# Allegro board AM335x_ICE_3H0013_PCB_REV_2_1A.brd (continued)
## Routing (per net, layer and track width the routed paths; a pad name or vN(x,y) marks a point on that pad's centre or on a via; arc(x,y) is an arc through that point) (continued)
GPMC_AD15: length 105.6
  TOP w0.121: U1.G6 v1(24.37,88.63) ; U14.U13 36.23,50.79 36.23,51.11 36.23,51.11 36.23,51.39 36.23,51.39 36.23,52.39 36.59,52.76 36.59,53.59 36.1,54.08 36.1,54.61 34.42,56.28 30.58,56.28 30.43,56.13 29.08,56.13 24.79,60.42 24.79,60.9 24.79,60.9 24.79,61.14 21.8,64.13 21.8,68.15 21.63,68.33 21.63,68.34 21.38,68.59 21.36,68.59 18.96,70.99 18.96,71.29 18.94,71.31 18.94,80.1 20.48,81.64 23.93,81.64 25,80.57 25.06,80.51 25.06,80.3 v1(25.22,80.14) 25.43,80.34 25.43,80.69 23.94,82.19 18.52,82.19 16.05,84.66 16.05,88.79 15.39,89.46 12.29,89.46 11.83,89.91 11.83,99.4 J4.29
  LYR4 w0.127: v1(25.22,80.14) 25.54,80.45 25.7,80.45 27.01,81.77 27.01,86.74 25.53,88.23 25.31,88.23 25.3,88.23 24.85,88.23 24.45,88.63 v1(24.37,88.63)
  BOTTOM w0.121: v1(25.22,80.14) 24.97,79.88 24.97,79.3 25.07,79.2 25.61,79.2 25.71,79.29 25.71,79.78 25.81,79.88 25.93,79.88 26.07,79.75 26.07,79.31 26.16,79.22 26.99,79.22 27.11,79.1 27.11,78.97 27,78.86 25.1,78.86 24.99,78.75 24.99,78.56 25.09,78.45 27.05,78.45 27.19,78.32 27.19,78.11 26.96,77.89 24.83,77.89 24.44,77.51 24.44,77.1 24.61,76.94 25.49,76.94 U26.26
GPMC_ADVN_ALE: length 76.6
  TOP w0.121: v1(41.77,49.25) U14.R7
  LYR3 w0.127: v1(41.77,49.25) 42.16,49.64 42.16,50.8 40.35,52.62 40.35,53.77 40.51,53.94 40.51,54.48 40.31,54.68 40.31,55.97 35.82,60.46 30.2,60.46 28.3,62.35 28.3,62.85 28.3,63.67 27.29,64.68 27.29,67.1 26.66,67.73 v1(26.64,67.73)
  LYR4 w0.127: J4.27 15.3,96.27 24.54,96.27 30.44,90.36 30.44,82.17 29.86,81.58 29.86,80.46 v1(26.77,77.37) 26.31,76.92 26.31,73.6 26.64,73.27 v1(26.64,67.73)
  BOTTOM w0.121: U26.25 v1(26.77,77.37) ; U26.48 26.2,68.17 v1(26.64,67.73)
GPMC_CSN0: length 49.5
  TOP w0.121: v1(28.64,82.18) 28.26,81.79 28.26,79.7 26.22,77.66 26.22,65.4 28.16,63.46 28.16,62.48 29.87,60.77 34.36,60.77 34.37,60.78 36,60.78 38.49,58.28 39.54,58.28 41.91,55.92 41.91,52.76 41.93,52.74 42.17,52.5 U14.V6 ; v1(23.57,83.83) U1.F1
  BOTTOM w0.121: v1(23.57,83.83) 24.21,83.19 28.31,83.19 R125.1 28.57,82.25 v1(28.64,82.18)
GPMC_CSN2: length 73.5
  TOP w0.121: U14.V9 40.01,51.49 40.01,53.49 39.72,53.77 39.72,54.43 39.74,54.45 39.74,55.28 38.56,56.46 37.53,56.46 35.6,58.38 29.45,58.38 26.25,61.58 26.25,62.27 v1(24.89,63.63)
  BOTTOM w0.121: J4.21 12.05,90.68 11.93,90.8 11.93,91.42 11.65,91.69 9.33,91.69 8.79,91.16 8.79,63.59 9.77,62.61 15.91,62.61 17.57,64.26 24.26,64.26 v1(24.89,63.63)
GPMC_NOR_A1: length 60.7
  TOP w0.121: v1(25.4,91.19) 30.06,86.53 30.06,81.92 29.7,81.55 29.61,81.55 29,80.94 29,71.01 27.57,69.58 27.57,65.41 29.07,63.91 29.07,62.75 30.3,61.51 33.87,61.51 33.88,61.51 36.61,61.51 39.11,59.02 39.94,59.02 40.16,58.8 40.95,58.8 43.08,56.67 43.08,54.12 43.43,53.77 v1(43.43,53.34) 43.43,53.21 43.37,53.15 43.37,50.85 U14.U5 ; U1.E6 v1(22.77,88.63)
  BOTTOM w0.121: v1(22.77,88.63) 22.77,89.32 24.77,91.32 25.26,91.32 v1(25.4,91.19) R102.2
GPMC_NOR_A2: length 57.4
  TOP w0.121: v1(19.57,84.63) U1.B2 ; v1(43.37,49.25) U14.R5
  LYR3 w0.127: v1(27.81,84.07) 29.12,82.77 29.12,71.2 28.56,70.64 28.56,66.37 27.87,65.69 27.87,65.27 28.56,64.58 28.56,62.53 30.2,60.88 36,60.88 40.82,56.07 40.82,53.92 40.58,53.68 40.58,53.02 42.98,50.62 42.98,49.64 v1(43.37,49.25)
  BOTTOM w0.121: R115.2 v1(27.81,84.07) 27.64,84.24 26.05,84.24 25.55,83.74 25.55,83.69 25.32,83.46 24.27,83.46 23.98,83.75 23.98,83.98 23.71,84.24 22.46,84.24 21.67,85.02 19.96,85.02 v1(19.57,84.63)
GPMC_OEN_REN: length 88.7
  TOP w0.121: v1(24.37,83.92) 24.29,83.92 U1.G1 ; v1(41.77,50.05) U14.T7
  LYR3 w0.127: v1(41.77,50.05) 41.77,50.58 39.89,52.46 39.89,53.45 39.73,53.62 39.73,53.93 39.72,53.93 39.72,54.26 39.9,54.44 39.9,55.84 35.66,60.08 30.04,60.08 26.86,63.26 26.86,66.92 26.22,67.56 26.22,68.35 26.97,69.1 26.97,72.16 27.91,73.11 27.91,78.74 28.32,79.15 28.32,81.69 28.13,81.88 28.13,81.89 27.92,82.11 27.92,83.31 27.23,84 27.23,87.58 25.04,89.76 22,89.76 ; v1(24.37,83.92) 24.45,83.92 24.78,84.24 24.78,85.58 23.98,86.38 23.98,88.97 23.54,89.41 22.35,89.41 22,89.76 ; 22,89.76 v1(21.92,89.76) 21.55,90.13 21.55,96.29 20.38,97.46 19.98,97.46 19.83,97.31 19.83,96.59 19.68,96.44 19.47,96.44 19.32,96.59 19.32,97.31 19.17,97.46 18.96,97.46 18.82,97.31 18.82,96.59 18.67,96.44 18.46,96.44 18.31,96.59 18.31,97.31 18.16,97.46 17.95,97.46 17.8,97.31 17.8,96.59 17.65,96.44 17.44,96.44 17.29,96.59 17.29,97.31 17.14,97.46 16.93,97.46 16.78,97.31 16.78,96.59 16.63,96.44 16.42,96.44 16.28,96.59 16.28,97.31 16.13,97.46 15.92,97.46 15.77,97.31 15.77,96.59 15.62,96.44 15.41,96.44 15.26,96.59 15.26,97.31 15.11,97.46 14.7,97.46 13.27,96.03 J4.25
GPMC_WEN: length 84.3
  TOP w0.121: U1.A4 v1(18.77,87.03) ; v1(19.38,90.73) 19.85,90.26 20.35,90.26 21.26,89.35 26.29,89.35 29.12,86.51 29.12,81.82 28.62,81.33 28.62,79.28 27.19,77.85 27.19,72.38 26.97,72.16 26.97,71.82 27.19,71.59 27.19,65.14 28.63,63.71 28.63,62.66 30.15,61.14 34.21,61.14 34.22,61.14 36.15,61.14 38.64,58.64 39.79,58.64 40,58.43 40.79,58.43 42.27,56.95 42.27,54.46 42.15,54.34 42.15,53.15 42.57,52.73 42.57,50.85 U14.U6
  LYR3 w0.127: J4.23 13.54,93.49 14.51,93.49 14.66,93.34 14.66,92.05 14.81,91.9 15.02,91.9 15.16,92.05 15.16,93.34 15.31,93.49 15.52,93.49 15.67,93.34 15.67,92.05 15.82,91.9 16.03,91.9 16.18,92.05 16.18,93.34 16.33,93.49 16.54,93.49 16.69,93.34 16.69,92.05 16.84,91.9 17.05,91.9 17.2,92.05 17.2,93.34 17.35,93.49 17.56,93.49 17.7,93.34 17.7,92.05 17.85,91.9 18.06,91.9 18.21,92.05 18.21,93.34 18.36,93.49 18.92,93.49 19.38,93.03 v1(19.38,90.73)
  BOTTOM w0.121: v1(19.38,90.73) 19.16,90.51 19.16,87.42 v1(18.77,87.03)
I2C0_SCL: length 250.6
  TOP w0.121: v1(3.08,61.68) 3.68,62.29 3.68,63.12 ; v1(33.77,38.85) U14.C16 ; R69.2 v1(11.43,21.34) ; U12.12 73.29,58.18 71.37,56.26 71.37,55.66 68.3,52.58 68.3,40.01 70.88,37.43 70.88,34.84 71.45,34.27 71.45,32.13 71.57,32.01 71.57,30.67 69.77,28.87 65.12,28.87 64.4,28.15 61.74,28.15 59.82,26.23 v1(59.82,25.78) 62.23,23.37 62.23,11.9 61.66,11.33 61.66,9.4 61.31,9.05 61.31,5.17 v1(58.8,2.67)
  LYR3 w0.127: v1(59.82,25.78) 59.4,26.2 50.04,26.2 48.65,24.81 43.97,24.81 42.57,26.21 37.8,26.21 37.31,26.69 36.91,26.69 36.66,26.45 36.66,26.28 v1(36.14,25.75) 36.14,25.77 35.71,26.19 31.24,26.19 30.65,26.79 28.96,26.79 27.07,24.9 22.44,24.9 21.2,23.66 17.92,23.66 16.88,22.62 12.71,22.62 v1(11.43,21.34)
  LYR4 w0.127: v1(36.14,25.75) 35.95,25.75 35.51,26.19 34.81,26.19 33.61,27.4 33.61,29.62 34.05,30.07 ; 34.05,30.07 v1(34.08,30.07) ; 34.05,30.07 34.05,30.52 33.75,30.82 33.75,32.26 34.21,32.71 34.21,36.71 33.77,37.15 v1(33.77,38.85) ; v1(11.43,21.34) 11.85,21.76 11.85,23.06 8.74,26.16 8.74,47.21 7.82,48.13 7.82,54.74 5.71,56.85 5.71,59.04 v1(3.08,61.68)
  BOTTOM w0.121: v1(3.08,61.68) 1.29,63.47 1.29,77.36 J3.6 3.71,79.78 3.71,93.97 8.63,98.9 8.63,100.65 10.08,102.1 17.84,102.1 21.08,98.86 v1(21.08,97.59) U25.6 ; v1(34.08,30.07) 34.04,30.02 34.04,29.72 R196.1 ; v1(59.82,25.78) U31.15 ; J17.5 59.06,2.93 v1(58.8,2.67)
I2C0_SDA: length 259.7
  TOP w0.121: v1(58.8,1.91) 58.38,2.32 58.38,3.52 59.9,5.04 59.9,8.8 60.62,9.51 60.62,11.34 61.09,11.81 61.09,22.48 v1(59.82,23.75) 59.18,24.38 59.18,26.29 62.14,29.25 63.55,29.25 63.7,29.1 63.73,29.1 63.75,29.09 64.27,29.09 64.28,29.1 64.84,29.1 65.55,29.81 68.37,29.81 71.21,32.65 71.21,34.08 70.63,34.65 70.63,36.98 67.88,39.73 67.88,52.58 71.01,55.71 71.01,56.63 73.21,58.83 U12.13 ; R72.2 14.99,21.08 14.99,21.95 v1(15.14,22.1) ; v1(30.18,26.14) 29.79,26.53 25.92,26.53 25.57,26.18 24.81,26.18 24.27,26.72 24.27,27.08 24.26,27.08 24.26,27.48 24.39,27.61 24.39,29.79 23.89,30.29 23.89,32.46 24.44,33 27.26,33 27.37,32.9 28.12,32.9 R61.1 28.98,33.76 29.7,33.76 30.43,34.49 30.43,35.37 31.79,36.73 31.79,37.35 32.43,37.99 32.59,37.99 32.97,38.37 32.97,38.85 U14.C17 ; U6.5 v1(2.41,65.51)
  LYR3 w0.127: v1(59.82,23.75) 58.71,22.64 45.77,22.64 43,25.41 41.94,25.41 41.52,24.99 31.69,24.99 30.54,26.14 v1(30.18,26.14) 29.79,26.54 29.17,26.54 27.29,24.65 22.69,24.65 21.41,23.37 18.59,23.37 17.59,22.36 15.91,22.36 15.64,22.1 v1(15.14,22.1)
  LYR4 w0.127: v1(2.41,65.51) 4.06,63.86 4.06,62.97 6.01,61.02 6.01,56.92 8.22,54.71 8.22,48.37 9,47.59 9,26.27 11.54,23.73 13.86,23.73 15.14,22.45 v1(15.14,22.1)
  BOTTOM w0.121: U25.7 v1(20.52,98.24) 20.52,99.06 17.73,101.85 10.18,101.85 8.95,100.62 8.95,98.56 6.81,96.42 6.81,93.02 5.98,92.2 4.28,92.2 3.95,91.87 3.95,77.49 J3.4 3.43,75.06 3.43,70.33 3.27,70.17 3.27,68.94 2.41,68.09 v1(2.41,65.51) ; U31.2 v1(59.82,23.75) ; 59.56,3.66 59.56,2.67 v1(58.8,1.91)
INDUS_INPUT0: length 8.8
  BOTTOM w0.121: J14.1 74.42,4.32 72.77,4.32 70.34,6.75 R226.1
INDUS_INPUT1: length 9.8
  TOP w0.121: R84.1 70.2,9.39 70.2,6.37 70.57,6 71.95,6 72.67,6.73 74.55,6.73 J14.3
INDUS_INPUT2: length 6.8
  TOP w0.121: R83.1 71.17,11.3 73.27,9.21 74.02,9.21 75.23,8 J14.5
INDUS_INPUT3: length 6.5
  TOP w0.121: J14.7 74.55,11.81 72.77,11.81 71.5,13.08 R81.1
INDUS_INPUT4: length 6.2
  TOP w0.121: J14.9 74.23,14.67 70.53,14.67 R80.1
INDUS_INPUT5: length 5.9
  TOP w0.121: R79.1 74.8,16.64 J14.11
INDUS_INPUT6: length 6.2
  TOP w0.121: J14.13 74.87,19.11 72.26,19.11 71.57,18.41 R74.1
INDUS_INPUT7: length 8.5
  TOP w0.121: R243.2 69.85,20.95 69.85,20.81 R68.1 71.38,20.31 72.14,19.56 74.68,19.56 J14.15
INDUS_INPUTSO: length 9.4
  TOP w0.121: U20.2 51.31,21.84 51.69,21.46 52.2,21.46 v1(53.85,19.81)
  BOTTOM w0.121: U35.23 57.24,17.79 57.02,18 57.02,18.88 56.09,19.81 v1(53.85,19.81)
IREF: length 3.1
  BOTTOM w0.121: J17.3 60.06,4.18 60.39,4.51 61.91,4.51 R232.1
JTAG_EMU0: length 109.9
  TOP w0.121: R25.1 75.43,67.01 74.8,67.64 72.21,67.64 72.02,67.45 72.02,67.24 v1(71.97,67.18) ; v1(35.37,38.85) U14.C14
  LYR3 w0.127: v1(20.83,28.45) 20.83,27.69 20.62,27.48 20.62,27.09 20.9,26.8 23.41,26.8 24.1,26.11 27.06,26.11 28.5,27.55 33.43,27.55 33.55,27.43 v1(34.16,27.43)
  LYR4 w0.127: v1(34.16,27.43) 34.16,27.71 33.86,28.01 33.86,29.25 34.69,30.08 34.69,32.83 35.47,33.61 35.47,33.96 34.98,34.45 34.98,38.46 v1(35.37,38.85) 35.6,38.85 36,38.45 36.33,38.45 36.57,38.21 36.57,37.09 42.67,30.99 48.97,30.99 49.57,30.39 52.84,30.39 53.18,30.05 59.31,30.05 59.65,30.39 60.27,30.39 61.71,31.84 64.55,31.84 66.34,33.63 66.34,34.62 68.13,36.41 68.35,36.41 69.15,37.21 69.15,57 69.4,57.26 69.4,64.62 v1(71.97,67.18)
  BOTTOM w0.121: J15.13 73.39,67.01 72.98,67.43 72.26,67.43 72.02,67.18 v1(71.97,67.18) ; R202.1 v1(20.83,28.45)
JTAG_EMU1: length 106.4
  TOP w0.121: v1(35.37,38.05) U14.B14 ; v1(72.26,65.49) 71.53,65.49 70.01,67.01 R24.1
  LYR3 w0.127: v1(21.13,25.53) 26.98,25.53 28.75,27.3 33.05,27.3 33.34,27.01 34.47,27.01 v1(34.82,27.36)
  LYR4 w0.127: v1(34.82,27.36) 34.82,27.41 34.11,28.12 34.11,29.04 35.01,29.94 35.01,32.2 35.01,32.21 35.01,32.55 35.01,32.56 35.01,32.79 35.72,33.5 35.72,35.52 35.37,35.88 v1(35.37,38.05) 35.69,37.73 35.69,37.62 42.57,30.73 48.74,30.73 49.33,30.14 52.74,30.14 53.08,29.8 59.42,29.8 59.76,30.14 60.37,30.14 61.82,31.58 65.01,31.58 66.85,33.43 66.85,34.12 67.3,34.57 67.62,34.57 67.91,34.86 67.91,35.6 69.4,37.1 69.4,56.9 69.66,57.15 69.66,63.82 71.32,65.49 v1(72.26,65.49)
  BOTTOM w0.121: J15.14 71.17,67.01 71.5,66.67 71.5,66.25 v1(72.26,65.49) ; R204.1 20.45,25.78 20.88,25.78 v1(21.13,25.53)
JTAG_TCK: length 113.2
  TOP w0.121: U14.A12 v1(36.97,37.25) ; v1(71.63,69.22) 71.75,69.22 72.77,70.23 75.18,70.23 75.47,69.94 R22.2 R23.2
  LYR3 w0.127: v1(17.72,33.25) 18.11,32.85 19,32.85 20.62,31.23 31.64,31.23 33.77,33.36 35.23,33.36 36.97,35.11 v1(36.97,37.25)
  LYR4 w0.127: v1(71.63,69.22) 69.15,66.73 69.15,57.4 68.89,57.15 68.89,37.31 68.25,36.66 68.03,36.66 65.84,34.48 65.84,33.76 64.33,32.25 60.79,32.25 59.86,31.31 59.86,31.25 58.91,30.3 53.29,30.3 52.95,30.65 49.9,30.65 49.3,31.24 42.98,31.24 v1(36.97,37.25)
  BOTTOM w0.121: v1(17.72,33.25) 17.66,33.19 17.66,27.76 15.36,25.46 14.59,25.46 13.46,24.34 R209.1
JTAG_TDI: length 99.9
  TOP w0.121: U14.B11 v1(37.77,38.05)
  LYR3 w0.127: v1(37.77,38.05) 38.16,37.66 38.16,33.85 36.03,31.71 v1(36.03,31.57)
  LYR4 w0.127: v1(37.77,38.05) 38.61,37.21 38.61,36.63 41.87,33.37 44.02,33.37 44.87,32.51 45.72,32.51 46.32,31.92 49.73,31.92 49.91,31.74 58.13,31.74 58.31,31.92 59.73,31.92 60.6,32.79 62.61,32.79 68.39,38.57 68.39,57.53 68.64,57.78 68.64,69.42 71.37,72.15 72.15,72.15 v1(72.9,72.9)
  BOTTOM w0.121: J15.3 73.36,73.36 v1(72.9,72.9) ; R192.1 20.5,30.81 29.08,30.81 29.15,30.88 29.17,30.88 29.19,30.89 29.19,30.89 29.97,30.89 30.35,31.27 32.57,31.27 33.19,31.9 34.59,31.9 35.21,31.27 35.73,31.27 v1(36.03,31.57)
JTAG_TDO: length 98
  TOP w0.121: U14.A11 v1(37.77,37.25)
  LYR3 w0.127: v1(36.02,32.41) 36.36,32.75 36.6,32.75 37.77,33.92 v1(37.77,37.25)
  LYR4 w0.127: v1(37.77,37.25) 38.35,36.66 38.35,36.53 42.69,32.19 45.15,32.19 45.69,31.66 49.48,31.66 50.15,30.99 53.32,30.99 53.66,30.65 56.99,30.65 57.59,31.24 58.52,31.24 58.86,31.58 59.76,31.58 60.7,32.53 62.71,32.53 68.64,38.46 68.64,57.4 68.89,57.66 68.89,68.97 71.25,71.33 72.73,71.33 v1(72.77,71.37)
  BOTTOM w0.121: R190.1 20.4,32 20.55,31.85 20.55,31.69 20.97,31.27 21.13,31.27 21.35,31.05 28.97,31.05 29.06,31.14 29.47,31.14 30.1,31.77 32.71,31.77 33.09,32.14 34.46,32.14 35.11,32.8 35.6,32.8 35.99,32.41 v1(36.02,32.41) ; v1(72.77,71.37) 73.32,70.82 J15.7
JTAG_TMS: length 102.3
  TOP w0.121: v1(37.77,38.85) U14.C11
  LYR3 w0.127: v1(37.77,38.85) 37.58,38.85 37.18,38.45 36.81,38.45 36.58,38.21 36.58,37.89 36.82,37.64 37.13,37.64 37.36,37.41 37.36,34.77 35.65,33.06 34.17,33.06 32,30.9 21.93,30.9 21.18,30.15 v1(21.1,30.15)
  LYR4 w0.127: v1(72.8,74.76) 70.65,74.76 66.63,70.74 66.63,64.14 67.91,62.86 67.91,57.81 67.88,57.78 67.88,38.92 62.76,33.81 60.47,33.81 60.12,33.45 57.95,33.45 57.93,33.44 55.28,33.44 54.79,32.95 54.3,32.95 54.16,33.08 52.51,33.08 51.98,33.62 44.93,33.62 44.12,34.42 42.31,34.42 37.89,38.85 v1(37.77,38.85)
  BOTTOM w0.121: v1(72.8,74.76) 74.68,74.76 J15.1 ; R194.1 20.93,29.97 v1(21.1,30.15)
JTAG_TRSTN: length 113.9
  TOP w0.121: R14.2 73.31,74.5 v1(72.8,74) ; v1(35.73,30.16) 35.73,30.27 36.44,30.98 36.44,32.84 36.07,33.21 36.07,34.84 38.57,37.34 38.57,38.05 U14.B10
  LYR4 w0.127: v1(72.28,62.14) 71.84,61.7 71.84,55.33 71.88,55.29 71.88,48.43 71.01,47.56 71.01,38.77 70.62,38.38 70.62,34.36 69.43,33.16 69.43,31.39 67.85,29.81 67.62,29.81 67.06,29.25 61.13,29.25 60.47,28.59 58.57,28.59 58.21,28.23 53.5,28.23 52.48,29.25 45.91,29.25 45.79,29.37 45.39,29.76 36.13,29.76 v1(35.73,30.16)
  BOTTOM w0.121: v1(72.28,62.14) 72.68,62.54 72.68,65.79 71.75,66.72 71.75,66.78 71.43,67.1 71.43,67.45 71.63,67.65 71.73,67.65 72.26,68.18 72.26,68.2 72.27,68.2 72.27,68.7 72.26,68.71 72.26,73.19 72.26,73.46 v1(72.8,74) 72.17,74.63 J15.2 ; R201.1 21.08,28.96 22.61,30.48 29.1,30.48 29.25,30.63 29.27,30.64 29.29,30.64 29.29,30.64 29.64,30.64 29.65,30.63 30.61,30.63 30.85,30.87 32.52,30.87 33.3,31.65 34.49,31.65 35.05,31.09 35.05,30.47 35.36,30.16 v1(35.73,30.16)
LATCH0_IN: length 59.4
  TOP w0.121: U14.D18 30.9,38.38 30.9,37.77 30.16,37.03 30.16,36.86 29.8,36.5 25.37,36.5 v1(24.52,37.35)
  LYR3 w0.127: v1(24.52,37.35) 22.12,39.75 18.67,39.75 15.79,42.63 15.79,54.05 11.43,58.41 11.43,63.01 7.24,67.2 7.24,74.3 5.52,76.01 J3.3
LATCH1_IN: length 64.5
  TOP w0.121: U14.D17 32.97,39.65 32.97,39.17 32.71,38.91 32.55,38.91 31.56,37.92 31.56,37.01 30.56,36.01 24.68,36.01 v1(23.62,37.07)
  LYR3 w0.127: v1(23.62,37.07) 21.92,38.77 19.01,38.77 15.44,42.35 15.44,53.44 10.38,58.5 10.38,61.53 5.46,66.45 5.46,70.95 3.93,72.49 3.93,77.46 J3.5
LCD_BST_CONV_CTL: length 65.7
  TOP w0.121: v1(34.57,41.25) U14.F15
  LYR3 w0.127: v1(34.57,41.25) 34.33,41.25 33.93,40.86 33.62,40.86 33.25,40.49 33.25,40.38 32.24,39.37 30.48,39.37 v1(30.35,39.24)
  LYR4 w0.127: v1(52.45,9.4) 49.95,11.9 31.07,11.9 30.82,12.15 30.82,14.72 33.87,17.77 35.39,17.77 35.88,18.25 35.88,19.95 35.39,20.43 35.15,20.68 31.02,20.68 29.56,22.13 29.56,24.26 29.8,24.5 29.8,25.93 29.76,25.96 29.76,29.28 29.59,29.46 29.59,29.83 29.37,30.04 29.37,31.44 28.79,32.02 28.79,32.41 29.27,32.9 29.27,36.23 30.64,37.59 30.64,38.96 v1(30.35,39.24)
  BOTTOM w0.121: R225.2 v1(52.45,9.4)
LED_1: length 111
  TOP w0.121: v1(34.57,45.25) U14.K15
  LYR3 w0.127: v1(26.37,42.69) 26.37,42.84 27.22,43.69 29.87,43.69 30.12,43.43 33.02,43.43 33.2,43.26 34.73,43.26 34.96,43.49 34.96,44.86 v1(34.57,45.25)
  BOTTOM w0.121: Q2.5 75.34,92.72 75.6,92.47 R107.2 77.12,91.84 77.12,89.21 75.72,87.81 72.52,87.81 71.68,88.65 69.69,88.65 67.76,90.57 65.39,90.57 64.98,90.16 64.98,89.43 62.62,87.07 58.54,87.07 58.38,87.23 57.45,87.23 57.28,87.07 53.36,87.07 52.06,88.38 47.67,88.38 45.21,85.92 45.21,82.55 43.55,80.89 43.55,78.2 40.37,75.02 36.81,75.02 36.81,75.02 33.77,75.02 32.28,73.53 32.28,71.6 32.54,71.33 32.54,68.57 32.14,68.16 32.14,64.36 32.08,64.29 32.08,62.16 28.71,58.79 28.71,55.81 26.4,53.5 26.4,46.99 25.59,46.18 25.59,43.58 25.4,43.4 25.4,42.67 25.65,42.42 26.1,42.42 v1(26.37,42.69)
LED_2: length 105.1
  TOP w0.121: v1(26.12,45.71) 27.62,44.21 29.86,44.21 30.22,43.86 31.67,43.86 31.86,44.05 U14.J18
  LYR4 w0.127: v1(70.4,86.87) 70.03,87.24 70.03,87.79 72.64,90.41 72.64,94.24 71.74,95.14 v1(71.41,95.14)
  BOTTOM w0.121: Q1.2 v1(71.41,95.14) R104.2 ; v1(26.12,45.71) 26.12,45.75 26.85,46.48 26.85,52.01 28.69,53.85 28.69,55.38 29.03,55.71 29.03,58.64 32.32,61.94 32.32,64.19 32.39,64.26 32.39,68.06 32.79,68.46 32.79,71.44 32.64,71.59 32.64,73.53 33.15,74.04 33.66,74.04 34.67,73.03 36.45,73.03 36.83,73.41 40.29,73.41 44.98,78.1 44.98,80.67 47.43,83.12 47.43,84.84 47.25,85.01 47.25,87.61 47.77,88.13 51.95,88.13 53.26,86.82 53.59,86.82 53.59,86.82 57.38,86.82 57.55,86.99 58.28,86.99 58.44,86.82 62.72,86.82 65.23,89.33 65.23,90.06 65.44,90.27 67.71,90.27 69.16,88.82 69.16,88.11 v1(70.4,86.87) R126.2
LED_3: length 102.9
  TOP w0.121: U14.K18 32.48,44.94 28.62,44.94 27.69,45.87 27.69,50.2 27.48,50.4 27.48,53.01 27.91,53.44 27.91,55.6 v1(28.19,55.88)
  BOTTOM w0.121: v1(28.19,55.88) 27.78,56.3 27.78,58.48 30.4,61.1 30.4,65.46 30.27,65.59 30.27,66.18 30.73,66.64 30.73,67.1 32.3,68.67 32.3,70.95 32.03,71.21 32.03,73.02 31.92,73.12 31.92,74.77 32.42,75.26 36.07,75.26 36.9,76.09 40.43,76.09 42.73,78.39 42.73,80.45 44.96,82.68 44.96,86.02 47.56,88.62 52.16,88.62 53.47,87.32 57.18,87.32 57.34,87.48 58.48,87.48 58.65,87.32 62.52,87.32 64.71,89.51 64.71,90.9 66.39,92.59 67.35,92.59 67.97,93.21 67.97,94.66 67.86,94.77 67.86,96.11 68.83,97.09 75.5,97.09 75.96,97.55 76.75,97.55 77.47,96.82 77.47,96.12 R103.2 Q1.5
LED_4: length 78.2
  TOP w0.121: v1(40.11,54.1) 40.26,53.95 40.26,51.42 40.23,51.39 40.23,50.91 U14.U9 ; v1(47.24,64.26) 46.86,63.88 TP37.1
  LYR4 w0.127: v1(50.42,71.88) 50.42,69.26 48.73,67.57 48.73,65.75 v1(47.24,64.26) 46.88,63.9 46.88,61.33 46.17,60.62 45.76,60.62 43.34,58.2 43.34,57.95 40.11,54.72 v1(40.11,54.1) ; v1(75.72,88.4) 73.77,86.45 70.23,86.45 70.19,86.49 v1(67.44,86.49)
  BOTTOM w0.121: v1(75.72,88.4) 76.49,89.17 R109.2 76.36,90.31 Q3.2 ; v1(67.44,86.49) 67.31,86.61 64.38,86.61 64.34,86.57 58.34,86.57 58.17,86.74 57.65,86.74 57.48,86.57 53.13,86.57 51.82,87.88 47.87,87.88 47.5,87.51 47.5,86.99 47.68,86.81 47.68,82.42 47.54,82.28 47.54,76.77 49.37,74.94 49.37,72.93 49.83,72.48 49.83,72.45 50.1,72.18 50.12,72.18 v1(50.42,71.88)
MDIO_CLK: length 17.1
  TOP w0.121: U14.M18 31.43,47.59 31.43,47.8 28.84,50.4 28.84,52.29 v1(29.25,52.7)
  BOTTOM w0.121: R149.2 29.53,55.56 29.53,55.03 29.25,54.75 v1(29.25,52.7)
MDIO_DATA: length 19.5
  TOP w0.121: U14.M17 32.97,46.85 32.49,46.85 31.88,47.46 31.88,48.61 30.44,50.04 30.35,50.04 29.42,50.97 v1(29.36,50.97)
  BOTTOM w0.121: R147.2 36.07,59.44 35.71,59.08 35.71,58.94 35.3,58.53 34.73,58.53 34.72,58.54 33.26,58.54 30.03,55.31 30.03,54.83 29.84,54.63 29.84,51.56 29.36,51.08 v1(29.36,50.97)
MMC0_CLK: length 57.8
  TOP w0.121: U24.6 17.18,3.46 v1(17.18,4.06) ; R58.1 26.29,40.13 v1(25.91,40.51)
  LYR4 w0.127: v1(25.91,40.51) 25.4,40.01 25.4,37.78 25.74,37.44 25.74,34.42 25.57,34.24 25.57,31.47 26.23,30.81 26.23,27.45 26.45,27.22 26.45,26.01 26,25.56 26,24.74 25.17,23.91 25.17,19.81 26.5,18.48 26.5,8.88 22.52,4.89 19.83,4.89 19.47,4.53 18.97,4.53 18.83,4.39 18.83,2.93 18.61,2.71 18.36,2.71 18.25,2.82 18.25,3.86 18.13,3.97 17.81,3.97 17.7,3.86 17.7,2.82 17.59,2.71 17.31,2.71 17.18,2.84 v1(17.18,4.06)
  BOTTOM w0.121: v1(17.18,4.06) 17.18,3.91 17.38,3.71 17.38,2.95 16.66,2.22 16.2,2.22 15.87,2.54 15.19,2.54 15.07,2.66 J16.5 13.97,2.66 13.08,1.78 R237.1
MMC0_CMD: length 65.8
  TOP w0.121: U24.3 18.76,2.95 19.21,3.4 19.59,3.4 19.81,3.18 19.85,3.18 v1(19.86,3.19) ; U14.G18 31.29,42.45 30.75,41.91 28.96,41.91 27.97,40.92 v1(27.97,40.47)
  LYR4 w0.127: v1(19.86,3.19) 19.86,2.88 20.27,2.47 20.62,2.47 21.66,3.51 26.88,3.51 29.43,6.06 29.43,16.47 28.34,17.56 28.34,18.88 27.79,19.43 27.79,21.94 27.24,22.49 27.24,25.36 27.47,25.59 27.47,27.65 27.24,27.87 27.24,31.23 27.14,31.34 27.14,33.1 27.35,33.31 27.35,39.85 v1(27.97,40.47)
  BOTTOM w0.121: v1(19.86,3.19) 19.84,3.19 20.04,3.39 29.07,3.39 J16.3 30.16,3.36 30.23,3.3 R235.1
MMC0_DAT0: length 65.4
  TOP w0.121: U24.7 16.84,2.95 v1(16.46,3.33) ; U14.G16 33.76,42.04 33.28,42.04 32.91,41.67 32.91,41.51 32.71,41.31 32.29,41.31 30.62,39.63 29.94,39.63 29,38.69 25.29,38.69 v1(24.83,38.23)
  LYR4 w0.127: v1(16.46,3.33) 16.65,3.51 16.65,4.25 17.46,5.06 19.07,5.06 19.57,5.55 19.57,6.45 19.71,6.6 20.25,6.6 20.36,6.49 20.36,5.74 20.47,5.63 20.63,5.63 20.74,5.74 20.74,6.49 20.85,6.6 21.01,6.6 21.12,6.49 21.12,5.74 21.23,5.63 21.39,5.63 21.5,5.74 21.5,6.49 21.62,6.6 21.77,6.6 21.88,6.49 21.88,5.74 22,5.63 22.15,5.63 22.27,5.74 22.27,6.49 22.38,6.6 23.43,6.6 26,9.17 26,18.27 24.17,20.1 24.17,23.86 25.49,25.18 25.49,25.77 25.95,26.22 25.95,27.01 25.72,27.24 25.72,30.6 25.06,31.26 25.06,34.46 25.23,34.63 25.23,37.23 24.83,37.64 v1(24.83,38.23)
  BOTTOM w0.121: v1(16.46,3.33) 15.73,4.06 J16.7 13.97,4.06 R236.1
MMC0_DAT1: length 64.9
  TOP w0.121: v1(16.4,2.72) 16.68,2.45 U24.8 ; v1(34.57,42.05) U14.G15
  LYR4 w0.127: v1(26.42,41.29) 25.96,41.29 24.1,39.43 24.1,37.11 24.98,36.23 24.98,34.79 24.8,34.61 24.8,30.44 25.46,29.78 25.46,27.14 25.69,26.91 25.69,26.33 25.28,25.92 24.9,25.92 23.36,24.38 23.36,24.38 23.36,22.49 23.2,22.34 23.2,20.37 25.34,18.24 25.34,10 22.41,7.07 19.05,7.07 15.9,3.93 15.9,3.51 15.92,3.5 15.92,3.21 v1(16.4,2.72)
  BOTTOM w0.121: v1(26.42,41.29) 26.91,41.79 28.92,41.79 29.4,41.3 30.04,41.3 30.4,41.66 32.64,41.66 33.03,42.05 v1(34.57,42.05) ; v1(16.4,2.72) 16.59,2.91 16.64,2.91 16.88,3.15 16.88,3.5 15.61,4.76 J16.8 14.16,4.76 13.72,4.32 13.08,4.32 R234.1
MMC0_DAT2: length 66.9
  TOP w0.121: U24.1 19.4,1.95 20.34,2.89 v1(20.45,2.89) ; v1(25.91,39.11) 28.82,39.11 30.29,40.58 30.73,40.58 31.81,41.65 U14.F18
  LYR4 w0.127: v1(25.91,39.11) 27.09,37.93 27.09,33.41 26.88,33.2 26.88,31.23 26.99,31.13 26.99,27.77 27.22,27.54 27.22,25.7 26.84,25.32 26.84,19.87 27.61,19.09 27.61,8.16 23.43,3.98 21.53,3.98 v1(20.45,2.89)
  BOTTOM w0.121: R231.1 30.23,5.33 29.66,4.76 J16.1 19.75,4.76 18.92,3.93 18.92,2.77 19.17,2.53 20.05,2.53 20.42,2.89 v1(20.45,2.89)
MMC0_DAT3: length 65.5
  TOP w0.121: v1(19.34,2.94) 18.84,2.45 U24.2 ; U14.F17 32.97,41.25 32.97,40.77 32.71,40.51 32.55,40.51 30.63,38.59 30.63,37.93 29.94,37.23 29.94,36.96 29.71,36.73 29.34,36.73 27.84,38.22 v1(26.07,38.22)
  LYR4 w0.127: v1(19.34,2.94) 19.4,3.01 19.4,3.73 20.06,4.39 22.79,4.39 27.11,8.71 27.11,18.88 26.58,19.41 26.58,25.42 26.96,25.8 26.96,27.44 26.73,27.66 26.73,31.02 26.63,31.13 26.63,36.79 26.25,37.16 26.25,37.65 26.07,37.83 v1(26.07,38.22)
  BOTTOM w0.121: v1(19.34,2.94) 19.34,3.88 19.84,4.38 20.19,4.38 20.5,4.06 J16.2 29.97,4.06 30.23,4.32 R233.1
MUX_MII_CTL1: length 47.5
  TOP w0.121: U9.1 33.26,66.54 33.53,66.8 33.53,67.81 v1(33.74,68.03) ; v1(31.15,55.7) 29.02,55.7 28.57,55.25 28.57,53.46 27.73,52.62 27.73,50.5 28.16,50.07 28.16,46.56 28.66,46.06 29.88,46.06 30.28,45.65 U14.L18 ; v1(43.98,64.12) 43.98,63.68 U11.1
  LYR4 w0.127: v1(31.15,55.7) 31.15,55.85 31.19,55.88 31.19,60.3 32.33,61.43 32.33,64.35 33.57,65.59 33.57,67.5 33.7,67.64 33.7,67.99 v1(33.74,68.03)
  BOTTOM w0.121: v1(33.74,68.03) 34.21,68.03 34.67,67.57 34.67,67.36 35.54,66.49 35.54,64.07 36.62,62.99 39.85,62.99 41.25,64.39 42.94,64.39 42.95,64.39 43.7,64.39 v1(43.98,64.12)
Net_52: length 0.6
  TOP w0.121: v1(19.57,85.43) 19.97,85.83
Net_53: length 0.6
  TOP w0.121: 20.77,86.63 v1(20.37,87.03)
Net_54: length 0.6
  TOP w0.121: v1(21.17,85.43) 21.57,85.83
NOR_READY: length 1.8
  TOP w0.121: v1(18.77,85.43) U1.A3
  BOTTOM w0.121: v1(18.77,85.43) 18.1,86.11 R111.1
NOR_RP: length 4.1
  TOP w0.121: U1.B4 v1(19.57,87.03)
  BOTTOM w0.121: R105.2 19.96,89.94 19.96,87.42 v1(19.57,87.03)
OSC0_OUT: length 8.2
  TOP w0.121: v1(37.85,55.11) 37.86,55.11 38.23,54.74 38.23,54.4 38.35,54.28 38.35,51.82 38.53,51.64 38.53,50.81 U14.U11
  BOTTOM w0.121: R156.1 35.56,56.2 36.09,55.67 36.09,55.24 36.23,55.11 v1(37.85,55.11)
OSC0_OUT1: length 9.2
  BOTTOM w0.121: C99.1 R156.2 36.13,57.28 36.14,57.29 36.79,57.29 Y3.1 37.13,57.93 37.87,58.67 40.9,58.67 41.91,57.67 R172.1
OSC1_IN: length 13.6
  TOP w0.121: U14.A6 42.49,37.33 42.49,35.05 42.75,34.79 42.76,34.79 43.06,34.5 43.06,32.81 43.26,32.61 43.26,29.1 42.67,28.51 42.67,27.99 v1(42.69,27.96) 42.95,27.96 43.05,28.07 C42.2
  BOTTOM w0.121: v1(42.69,27.96) 42.69,27.93 42.94,27.69 43.4,27.69 Y4.4
OSC1_OUT: length 4.7
  TOP w0.121: R64.1 44.83,33.4 44.83,33.41 44.7,33.53 44.7,33.54 44.41,33.83 44.41,34.59 43.77,35.22 U14.A4
OSC1_OUT1: length 3.9
  TOP w0.121: R64.2 v1(44.83,31.71) 44.58,31.46 C40.2
  BOTTOM w0.121: v1(44.83,31.71) 44.77,31.71 43.81,30.76 43.81,30.64 Y4.1
PGOOD_VTT: length 9.3
  TOP w0.121: TP22.1 69.89,43.86 v2(69.89,43.35)
  BOTTOM w0.121: U29.9 68.83,37.41 69.15,37.74 69.15,38.04 69.2,38.1 69.2,40.6 69.6,40.99 R184.1 69.6,43.05 v2(69.89,43.35)
PH: length 1.4
  TOP w0.635: C56.2 43.81,16.51
PMIC_I2C_SCL: length 10.1
  TOP w0.121: R69.1 R70.1 13.08,18.92 13.84,18.92 15.88,16.88 15.88,16.81 16.13,16.56 16.13,13.72 16.65,13.19 U22.9
PMIC_I2C_SDA: length 9
  TOP w0.121: R71.1 R72.1 14.48,18.8 16.13,17.14 16.13,16.91 16.38,16.66 16.38,13.84 17.05,13.17 U22.8
PMIC_INTN: length 8.6
  TOP w0.121: U22.45 21.45,10.65 22.35,11.56 22.35,16.26 TP27.1
PMIC_PWR_EN: length 48.6
  TOP w0.121: v1(20.7,13.21) 20.12,12.63 U22.1 ; v1(42.57,38.85) U14.C6
  LYR3 w0.127: v1(20.7,13.21) 30.3,13.21 31.19,12.32 v1(31.24,12.32)
  LYR4 w0.127: v1(42.21,24.97) 39.5,22.26 39.5,16.86 34.95,12.32 v1(31.24,12.32)
  BOTTOM w0.121: v1(42.21,24.97) 41.87,25.32 41.87,27.46 41.98,27.58 41.98,27.76 41.98,27.81 42.17,28 42.17,28.02 42.19,28.04 42.19,28.17 42.31,28.29 42.31,28.4 42.37,28.45 42.37,29 42.27,29.1 42.27,29.18 42.22,29.23 42.22,32.15 42.52,32.45 44.01,32.45 44.19,32.63 44.19,33.15 43.94,33.41 43.94,35.94 42.97,36.92 42.97,38.45 v1(42.57,38.85)
PMIC_RESETOUTN: length 49.2
  TOP w0.121: U14.B15 v1(34.57,38.05) ; v1(21.84,8.38) 21.57,8.65 U22.40
  LYR3 w0.127: v1(22.86,34.67) 28.27,34.67 29.54,35.95 33.64,35.95 34.57,36.87 v1(34.57,38.05)
  LYR4 w0.127: v1(22.86,34.67) 22.44,34.25 22.44,33.28 22.87,32.85 22.87,22.72 22.71,22.56 22.71,17.21 20.03,14.54 20.03,13.75 20,13.72 20,10.22 v1(21.84,8.38)
  BOTTOM w0.121: C194.1 24.51,34.04 24.64,33.91 25.02,33.91 ; v1(22.86,34.67) 23.88,33.66 24.9,33.66 25.02,33.78 25.02,33.91 ; 25.02,33.91 25.4,33.91 25.53,34.04 R187.2
PMIC_SLEEP: length 7.1
  TOP w0.121: TP31.1 21.08,2.04 21.83,2.79 21.83,2.97 v1(21.81,2.97) ; v1(21.84,7.49) 21.8,7.45 U22.37
  LYR3 w0.127: v1(21.81,2.97) 21.84,3.01 21.84,4.64 21.83,4.66 21.83,7.48 v1(21.84,7.49)
PMICSR_I2C_SCL: length 2.4
  TOP w0.121: U22.11 15.85,13.23 15.11,13.97 TP29.1
PMICSR_I2C_SDA: length 4.4
  TOP w0.121: U22.10 16.25,13.21 15.88,13.59 15.88,15.75 TP28.1
PR1_MDIO_DATA: length 18.4
  TOP w0.121: v1(36.17,50.05) U14.T13
  LYR4 w0.127: v1(36.17,50.05) 35.99,50.23 35.99,50.31 35.38,50.92 33.85,50.92 32.46,52.31 31.76,52.31 30.44,53.64 30.44,53.79 v1(30.4,53.83)
  BOTTOM w0.121: v1(30.4,53.83) 30.44,53.87 30.44,54.06 30.7,54.32 31.03,54.32 31.04,54.33 31.48,54.33 31.84,54.69 31.84,56.41 33.57,58.14 35.28,58.14 R146.2
PR1_MDIO_MDCLK: length 16.8
  TOP w0.121: v1(29.84,57.36) 29.93,57.36 30.08,57.51 35.24,57.51 37.32,55.42 37.32,54.22 37.43,54.11 37.43,51.31 U14.V12
  BOTTOM w0.121: v1(29.84,57.36) 30.18,57.36 32.77,59.94 R150.2
PR1_MII0_RXLINK_SPEED: length 50
  TOP w0.121: U14.V2 45.37,51.59 45.78,52 45.78,54.03 47.9,56.15 49.51,56.15 50.58,55.08 51.21,55.08 52.45,56.32 52.45,59.18 52.19,59.45 v1(52.19,59.69) ; U4.2 69.56,67.91 69.22,67.56 65.91,67.56 v1(65.79,67.44)
  LYR3 w0.127: v1(52.19,59.69) 52.45,59.43 52.45,55.31 53.91,53.85 57.7,53.85 57.95,54.1 57.95,55.16 58.62,55.83 58.62,58.2 64.4,63.98 64.4,66.05 v1(65.79,67.44)
  BOTTOM w0.121: U38.9 52.02,62.3 52.02,60.82 52.19,60.66 v1(52.19,59.69)
PR1_MII1_CLK: length 26.9
  TOP w0.121: v1(33.12,54.1) 33.12,53.75 32.92,53.54 32.92,52.62 33.77,51.77 33.77,50.85 U14.U16 ; v1(36.49,70.1) U2.38
  LYR4 w0.127: v1(33.12,54.1) 32.74,54.48 32.74,54.48 32.33,54.88 32.33,57.26 34.83,59.76 36.53,59.76 38.64,61.87 38.64,62.18 38.71,62.25 38.71,62.67 38.61,62.77 38.61,66.3 38.05,66.86 38.05,68.33 38.04,68.35 36.49,69.9 v1(36.49,70.1)
PR1_MII1_COL_RMII2_CRS_DV: length 19.6
  TOP w0.121: U14.T17 33.05,49.65 32.71,49.31 32.43,49.31 29.84,51.9 29.84,54.48 v1(29.11,55.21) ; v1(28.39,65.54) 28.39,65.38 U9.9
  LYR4 w0.127: v1(29.11,55.21) 29.11,55.95 28.39,56.67 v1(28.39,65.54)
PR1_MII1_CRS: length 39.7
  TOP w0.121: v1(42.57,49.25) U14.R6 ; v1(37.77,70.11) 37.49,70.4 U2.40 ; v1(29.98,62.69) 29.84,62.83 29.81,62.83 29.48,63.16 U9.10
  LYR3 w0.127: v1(37.77,70.11) 37.32,70.11 36.46,69.26 36.46,68.82 32.32,64.68 30.52,64.68 29.48,63.64 29.48,63.15 29.81,62.83 29.84,62.83 v1(29.98,62.69)
  LYR4 w0.127: v1(29.98,62.69) 29.99,62.68 29.99,62.29 30.29,61.99 30.29,54.59 31.23,53.65 31.23,53.3 31.93,52.6 32.53,52.6 33.99,51.15 41.23,51.15 42.18,50.2 42.18,49.89 42.57,49.49 v1(42.57,49.25)
PR1_MII1_RXD0: length 46.6
  TOP w0.121: v1(33.37,55.82) 33.59,55.6 33.59,54.47 33.51,54.39 33.51,53.82 33.14,53.45 33.14,52.86 33.27,52.72 34.06,52.72 34.17,52.61 U14.V16 ; U2.43 v1(38.98,69.9) ; U11.10 40.66,60.84 40.22,60.4 39.96,60.4 39.81,60.56 39.81,61.2 39.72,61.28 v1(39.32,61.28)
  LYR4 w0.127: v1(33.37,55.82) 33.4,55.85 33.4,55.86 33.7,56.17 33.7,56.32 33.52,56.5 33.52,56.66 33.63,56.77 33.79,56.77 33.97,56.59 34.13,56.59 34.24,56.71 34.24,56.86 34.06,57.04 34.06,57.2 34.17,57.31 34.33,57.31 34.57,57.07 34.6,57.07 34.61,57.08 34.88,57.08 35.04,57.23 35.04,58.14 35.15,58.25 35.41,58.25 35.52,58.14 35.52,57.31 35.71,57.12 36.2,57.12 36.46,57.38 36.46,57.53 36.07,57.92 36.07,58.08 36.18,58.19 36.34,58.19 36.73,57.8 36.89,57.8 37,57.92 37,58.07 36.61,58.46 36.61,58.62 36.72,58.73 36.88,58.73 37.27,58.34 37.42,58.34 37.54,58.45 37.54,58.61 37.15,59 37.15,59.16 37.26,59.27 37.42,59.27 37.81,58.88 37.96,58.88 38.45,59.37 38.45,59.57 38.15,59.87 38.15,60.11 v1(39.32,61.28) 39.54,61.5 39.54,62.29 39.54,62.29 39.54,64.19 39.39,64.34 39.12,64.34 39.02,64.44 39.02,64.75 39.12,64.85 39.39,64.85 39.57,65.03 39.57,66.39 39.38,66.58 38.88,66.58 38.7,66.75 38.7,66.97 38.84,67.11 39.8,67.11 40.02,67.33 40.02,68.03 39.8,68.24 38.65,68.24 38.46,68.44 38.46,68.7 38.61,68.85 40.02,68.85 40.2,69.03 40.2,69.25 40.05,69.41 38.6,69.41 38.46,69.55 38.46,71.4 38.59,71.54 38.8,71.54 38.98,71.35 v1(38.98,69.9)
  BOTTOM w0.121: R135.1 38.98,69.85 v1(38.98,69.9)
PR1_MII1_RXD1: length 49.2
  TOP w0.121: 39.49,70.49 39.49,69.35 R28.1 ; 39.49,70.49 U2.44 ; 39.49,70.49 v1(39.48,70.49) 39.49,70.49 ; v1(34.57,50.05) U14.T15 ; U9.6 30.12,67.67 30.12,69.34 30.73,69.95 v1(31.38,69.95)
  LYR3 w0.127: v1(39.48,70.49) 39.48,71.01 39.22,71.27 34.98,71.27 34.83,71.12 34.83,70.17 34.68,70.02 34.47,70.02 34.32,70.17 34.32,71.12 34.17,71.27 33.96,71.27 33.81,71.12 33.81,70.17 33.67,70.02 33.45,70.02 33.31,70.17 33.31,71.12 33.16,71.27 32.95,71.27 32.8,71.12 32.8,70.17 32.65,70.02 32.44,70.02 32.29,70.17 32.29,71.12 32.14,71.27 31.84,71.27 31.38,70.81 v1(31.38,69.95)
  LYR4 w0.127: v1(31.38,69.95) 29.48,69.95 27.72,68.18 27.72,55.04 32.7,50.05 v1(34.57,50.05)
PR1_MII1_RXD2: length 44.6
  TOP w0.121: v1(34.2,55.48) 33.95,55.23 33.95,54.74 34.08,54.61 34.3,54.39 34.3,54.37 34.42,54.25 34.42,53.18 34.57,53.03 34.57,50.85 U14.U15 ; U2.45 v1(39.98,70.74)
  LYR4 w0.127: v1(34.2,55.48) 34.22,55.5 34.38,55.5 34.66,55.78 34.97,55.78 35.08,55.89 35.08,56.2 35.19,56.32 35.35,56.32 35.46,56.2 35.46,55.89 35.57,55.78 35.98,55.78 39.98,59.78 39.98,60.73 40.36,61.11 40.36,61.62 40.48,61.74 40.99,61.74 41.08,61.65 41.08,61.38 41.17,61.29 41.54,61.29 41.68,61.43 41.68,62.43 41.25,62.86 40.54,62.86 40.36,63.04 40.36,63.87 40.48,63.99 41.55,63.99 41.66,64.1 41.66,64.34 41.53,64.48 40.46,64.48 40.36,64.58 40.36,64.86 40.46,64.96 40.98,64.96 41.23,65.21 41.23,66.06 40.96,66.33 40.07,66.33 39.95,66.45 39.95,66.73 39.96,66.73 40.15,66.92 40.8,66.92 40.92,66.81 41.75,66.81 41.88,66.93 41.88,67.19 41.77,67.3 41.11,67.3 41,67.41 41,67.57 41.11,67.68 41.9,67.68 42.01,67.79 42.01,67.95 41.92,68.04 40.56,68.04 40.45,68.15 40.45,68.31 40.56,68.42 41.64,68.42 41.77,68.55 41.77,68.71 41.66,68.82 40.67,68.82 40.59,68.91 40.59,69.12 40.67,69.2 41.66,69.2 41.77,69.32 41.77,69.58 41.67,69.68 40.31,69.68 39.98,70.01 v1(39.98,70.74)
  BOTTOM w0.121: R134.1 39.98,69.87 v1(39.98,70.74)
PR1_MII1_RXD3_RMII2_TXD0: length 19.9
  TOP w0.121: U11.12 41.66,59.99 v1(41.53,59.85) ; v1(34.37,54.92) 34.37,54.91 34.54,54.74 34.54,54.45 34.77,54.22 34.86,54.22 35.28,53.8 35.28,53.47 35.13,53.32 35.13,51.41 U14.V15
  LYR4 w0.127: v1(34.37,54.92) 34.37,54.92 34.52,54.77 34.52,54.35 34.71,54.15 36.15,54.15 37.9,55.9 38.05,55.9 38.47,55.48 38.62,55.48 38.74,55.6 38.74,55.75 38.33,56.16 38.33,56.33 38.44,56.44 38.59,56.44 39.01,56.02 39.16,56.02 39.28,56.13 39.28,56.29 38.87,56.7 38.87,56.86 38.98,56.98 39.13,56.98 39.55,56.56 39.7,56.56 39.81,56.67 39.81,56.83 39.41,57.24 39.41,57.4 41.51,59.51 41.51,59.84 v1(41.53,59.85)
PR1_MII1_RXDV_RMII2_RXD1: length 22.2
  TOP w0.121: U14.T16 33.71,50.11 32.43,50.11 30.79,51.75 30.79,54.97 v1(30.72,55.03) ; U9.7 29.48,68.13 29.67,68.31 v1(29.71,68.31)
  LYR4 w0.127: v1(29.71,68.31) 30.31,67.7 30.31,66.23 30.26,66.18 30.26,65.45 30.73,64.98 30.73,55.32 30.72,55.31 v1(30.72,55.03)
PR1_MII1_RXER_RMII2_RXD0: length 16.9
  TOP w0.121: v1(32.75,55.75) 32.85,55.75 33.23,55.37 33.23,54.62 33.1,54.49 32.89,54.49 32.55,54.15 32.55,53.03 32.29,52.77 32.28,52.77 32.28,52.09 32.42,51.95 33.1,51.95 33.37,51.68 U14.V17 ; v1(39.12,62.12) 39.12,62.11 U11.9
  LYR4 w0.127: v1(32.75,55.75) 32.77,55.77 32.77,57.04 34.44,58.71 36.14,58.71 39.09,61.66 39.09,62.08 v1(39.12,62.12)
PR1_MII1_TXCLK_RMII2_TXEN: length 32.4
  TOP w0.121: v1(36.17,49.25) U14.R13 ; v1(44.97,63.84) 44.92,63.9 44.92,64.52 44.04,65.39 43.78,65.39 43.26,65.91 42.45,65.91 42.16,65.61 U11.4
  LYR3 w0.127: v1(36.17,49.25) 36.41,49.25 36.81,48.86 37.3,48.86 37.41,48.97 38.3,48.97 38.41,48.86 38.73,48.86 43.53,48.86 43.76,49.09 43.76,49.4 44.02,49.66 45.13,49.66 45.36,49.89 45.36,50.21 45.13,50.44 44.19,51.39 42.71,52.87 42.46,52.87 42.08,53.24 42.08,57.42 43.43,58.77 43.43,60.87 44.92,62.36 44.92,63.78 v1(44.97,63.84)
PR1_MII1_TXD0_RMII2_TXD1: length 27.1
  TOP w0.121: v1(35.37,49.25) U14.R14 ; U9.4 30.9,67.62 v1(30.9,68.57)
  LYR4 w0.127: v1(35.37,49.25) 35.53,49.42 35.53,49.5 35.76,49.73 35.76,50.21 35.29,50.69 33.69,50.69 32.29,52.08 31.58,52.08 29.91,53.75 29.91,56.5 29.19,57.22 29.19,68.39 29.42,68.62 29.42,68.67 29.72,68.96 30.51,68.96 v1(30.9,68.57)
PR1_MII1_TXD1: length 54.2
  TOP w0.121: U9.3 31.48,68.64 v1(31,69.12) ; v1(41.23,73.53) 41.4,73.7 41.4,73.94 42.28,74.82 U2.4 ; v1(35.37,50.05) U14.T14
  LYR3 w0.127: v1(31,69.12) 30.96,69.16 30.96,71.22 31.93,72.19 33.92,72.19 34.07,72.34 34.07,72.92 34.22,73.06 34.43,73.06 34.58,72.92 34.58,72.34 34.73,72.19 34.94,72.19 35.09,72.34 35.09,72.92 35.24,73.06 35.45,73.06 35.6,72.92 35.6,72.34 35.75,72.19 35.96,72.19 36.1,72.34 36.1,72.92 36.25,73.06 36.46,73.06 36.61,72.92 36.61,72.34 36.76,72.19 36.97,72.19 37.12,72.34 37.12,72.92 37.27,73.06 37.48,73.06 37.63,72.92 37.63,72.34 37.78,72.19 37.99,72.19 38.14,72.34 38.14,72.92 38.29,73.06 38.5,73.06 38.64,72.92 38.64,72.34 38.79,72.19 39,72.19 39.15,72.34 39.15,72.92 39.3,73.06 39.51,73.06 39.66,72.92 39.66,72.34 39.81,72.19 40.92,72.19 41.23,72.49 v1(41.23,73.53)
  LYR4 w0.127: v1(35.37,50.05) 34.98,50.44 32.79,50.44 29.59,53.65 29.59,53.7 29.53,53.76 29.53,56.34 28.81,57.06 28.81,66.1 28.7,66.21 28.34,66.21 28.23,66.32 28.23,66.48 28.34,66.59 28.7,66.59 28.81,66.7 28.81,67.58 28.7,67.69 28.43,67.69 28.31,67.8 28.31,67.96 28.43,68.07 28.7,68.07 28.81,68.18 28.81,68.74 29.64,69.57 30.76,69.57 31,69.32 v1(31,69.12)
PR1_MII1_TXD2: length 53
  TOP w0.121: v1(34.93,54.61) 35.51,54.04 35.51,53.38 35.43,53.3 35.43,50.79 U14.U14 ; v1(44.57,75.14) 44.51,75.14 44.32,75.32 U2.5
  LYR4 w0.127: v1(34.93,54.61) 34.98,54.66 36,54.66 40.96,59.62 40.96,59.87 41.39,60.31 41.71,60.31 41.86,60.16 41.86,60.11 42.42,59.55 42.49,59.55 42.49,59.54 42.64,59.54 42.64,59.55 43.61,59.55 45.12,61.06 45.12,62.51 45.62,63.01 45.62,66.92 45.89,67.19 47.5,67.19 48.26,67.94 48.26,68.27 48.13,68.4 47.86,68.4 47.7,68.57 47.7,68.78 47.85,68.93 48.96,68.93 49.11,69.08 49.11,69.29 48.96,69.44 47.85,69.44 47.7,69.58 47.7,69.79 47.85,69.94 49.75,69.94 49.9,70.09 49.9,70.3 49.75,70.45 47.85,70.45 47.7,70.6 47.7,70.81 47.85,70.96 49.75,70.96 49.9,71.11 49.9,71.32 49.75,71.47 47.85,71.47 47.7,71.62 47.7,71.83 47.85,71.98 48.96,71.98 49.11,72.12 49.11,72.47 48.84,72.74 46.75,72.74 46.4,73.09 46.4,74.98 45.73,75.65 45.08,75.65 v1(44.57,75.14)
PR1_MII1_TXD3: length 52.3
  TOP w0.121: U14.V14 35.77,54.33 34.88,55.21 34.88,55.21 v1(34.87,55.22) ; U2.6 v1(44.07,75.82)
  LYR4 w0.127: v1(44.07,75.82) 41.27,75.82 41.06,75.61 41.06,74.29 40.85,74.08 40.23,74.08 40.1,73.95 40.1,72.85 39.96,72.7 39.74,72.7 39.6,72.85 39.6,73.91 39.43,74.08 39.22,74.08 39.09,73.95 39.09,72.85 38.94,72.7 38.73,72.7 38.58,72.85 38.58,73.91 38.41,74.08 37.47,74.08 37.2,73.81 37.2,72.62 37.61,72.21 42.92,72.21 43.55,71.59 43.55,69.75 43.8,69.49 43.8,68.94 43.55,68.68 43.55,66.88 42.66,66 42.42,66 42.08,65.66 42.08,65.17 42.49,64.76 43.33,64.76 43.54,64.55 43.54,60.27 43.2,59.93 42.58,59.93 42.24,60.27 42.24,60.45 41.78,60.91 40.79,60.91 40.36,60.48 40.36,59.56 36.02,55.22 v1(34.87,55.22)
PR1_MII1_TXEN_RMII2_RXERR: length 24.5
  TOP w0.121: v1(32.81,55.1) 32.77,55.1 32.77,55.02 32.21,55.02 31.62,54.43 31.62,54.02 31.23,53.63 31.23,52.04 32.42,50.85 32.97,50.85 U14.U17 ; U11.7 v1(40.66,65.41)
  LYR4 w0.127: v1(32.81,55.1) 32.84,55.1 33.29,54.65 33.53,54.65 33.78,54.9 33.78,55.71 34.77,56.7 36.34,56.7 39.6,59.95 39.6,60.88 39.98,61.27 39.98,65.83 40.11,65.95 40.4,65.95 40.66,65.69 v1(40.66,65.41)
PR1_MII_CTL: length 50.1
  TOP w0.121: v1(54.75,59.94) 54.37,60.33 52.32,60.33 51.94,60.71 R278.2 ; v1(54.75,59.94) 54.1,59.29 U37.1 ; v1(54.75,59.94) U37.19 ; U14.J17 v1(33.77,44.45)
  LYR3 w0.127: v1(54.75,59.94) 54.24,60.45 50.69,60.45 49.8,59.56 48.4,59.56 v1(47.64,58.8) 46.99,59.45 v1(46.99,60.83)
  LYR4 w0.127: v1(33.77,44.45) 33.77,44.69 34.18,45.1 34.18,46.66 34.99,47.48 34.99,48.27 34.98,48.29 34.98,48.61 35.22,48.86 35.53,48.86 35.78,49.1 35.78,49.41 36.01,49.64 36.45,49.64 36.58,49.77 36.58,50.29 36.73,50.44 38.73,50.44 41.13,50.44 41.38,50.2 41.38,49.89 41.62,49.64 41.93,49.64 42.18,49.4 42.18,49.09 42.41,48.86 43.53,48.86 43.78,49.1 43.78,50.81 v1(46.23,53.26)
  BOTTOM w0.121: v1(47.64,58.8) U38.19 47.64,55.38 R277.2 46.61,53.64 v1(46.23,53.26) ; U38.1 46.99,62.46 v1(46.99,60.83)
PROFI_GND: length 25.6
  TOP w0.584: J7.1 22.15,45.26 22.15,48.01 21.39,48.77 6.65,48.77 4.06,46.18 J9.5
PROFIBUS_A: length 31.5
  LYR3 w0.381: J8.1 17.4,45.09 17.4,52.06 17.69,52.35 17.69,53.8 14.06,57.43 13.31,57.43 v1(12.06,58.67) 12.93,58.67 13.94,59.69 17.14,59.69 v1(17.91,60.45)
  BOTTOM w0.381: U28.12 v1(12.06,58.67) ; R152.1 v1(17.91,60.45)
PROFIBUS_B: length 30.2
  TOP w0.121: v1(5.71,42.42) 5.32,42.02 J9.8
  LYR3 w0.127: v1(6.6,58.67) 7.02,58.25 7.02,43.73 v1(5.71,42.42)
  BOTTOM w0.121: R153.2 v1(6.6,58.67) 7.37,57.91 12.19,57.91 13.34,59.05 13.34,60.33
PRUETH0_ACTLED: length 36.1
  TOP w0.121: U3.26 51.98,78.32 v1(52.07,78.23)
  LYR3 w0.127: v1(60.01,101.22) 58.17,101.22 56.96,100.01 56.96,95.38 52.9,91.31 52.9,85.53 52.04,84.68 52.04,81.23 51.85,81.04 51.85,78.45 v1(52.07,78.23)
  BOTTOM w0.121: J2.12 60.59,101.8 v1(60.01,101.22) R92.1
PRUETH0_COL: length 28.3
  TOP w0.121: U3.42 v1(54.87,70.23) 54.74,70.1 54.38,70.1 54.04,69.77 53.77,69.77 R30.1 ; U8.1 36.59,66.82 v1(37.08,67.31)
  BOTTOM w0.121: v1(54.87,70.23) 54.87,69.66 54.54,69.34 52.92,69.34 52.46,69.8 52.45,69.8 52.43,69.81 50.62,69.81 49.03,71.4 37.21,71.4 36.96,71.15 36.96,69.81 36.94,69.79 36.94,67.45 v1(37.08,67.31)
PRUETH0_CRS: length 66.6
  TOP w0.121: v1(53.87,70.19) U3.40 ; v1(25.85,42.9) 25.87,42.9 25.87,42.95 26.78,43.85 29.78,43.85 30,43.64 32.98,43.64 U14.H17 ; v1(42.55,54.1) 43.02,53.63 43.02,53.17 43.05,53.13 43.05,51.33 U14.V5
  LYR3 w0.127: v1(25.85,42.9) 25.87,42.9 25.87,42.84 25.65,43.06 25.65,47.92 26.05,48.32 26.05,50.76 29.64,54.34 30.9,54.34 31.01,54.46 v1(32.2,54.46) ; v1(42.55,54.1) 42.55,55.67 45.05,58.17 45.05,61.81 46.74,63.5 48.3,63.5 48.81,64.01 48.81,68.91 50.46,70.57 51.24,70.57 51.84,71.16 53.54,71.16 53.87,70.83 v1(53.87,70.19)
  LYR4 w0.127: v1(42.55,54.1) 42.18,53.73 42.18,53.34 40.95,52.12 34.06,52.12 33.01,53.17 33.01,53.65 v1(32.2,54.46)
PRUETH0_INT: length 3
  TOP w0.121: U3.7 60.84,76.32 R19.1
PRUETH0_JTCK: length 2.6
  TOP w0.121: TP15.1 60.96,77.09 60.7,76.82 U3.8
PRUETH0_JTDI: length 6.6
  TOP w0.121: TP7.1 62.55,81.98 61.56,81.98 60.42,80.84 60.42,78.99 60.25,78.82 U3.12
PRUETH0_JTDO: length 3
  TOP w0.121: TP13.1 60.69,77.32 U3.9
PRUETH0_JTMS: length 3.7
  TOP w0.121: TP11.1 61.14,79.18 61.14,78.69 60.27,77.82 U3.10
PRUETH0_JTRSTN: length 4.6
  TOP w0.121: U3.11 60.26,78.32 60.78,78.84 60.78,80.21 TP9.1
PRUETH0_RESETN: length 28.6
  TOP w0.121: U5.4 47.74,71.39 47.05,72.07 47.05,72.9 46.61,73.35 46.61,75.56 v1(46.61,75.56) 46.61,75.57 46.61,75.57 47.3,76.26 48.2,76.26 48.48,76.55 49.62,76.55 49.9,76.82 U3.29 ; U2.29 v1(32.77,76.82)
  LYR4 w0.127: v1(46.61,75.56) 42.76,79.41 36.27,79.41 33.69,76.82 v1(32.77,76.82)
PRUETH0_RXCLK: length 28.2
  TOP w0.121: v1(53.13,70.24) 52.87,70.49 U3.38 ; U14.V4 43.77,52.27 44.58,53.07 44.58,53.91 44.06,54.43 44.06,55.87 47.75,59.56 49.08,59.56 v1(49.59,60.07)
  LYR3 w0.127: v1(49.59,60.07) 49.59,60.47 52.62,63.5 52.62,63.95 52.87,64.2 52.87,69.98 v1(53.13,70.24)
  BOTTOM w0.121: U38.5 v1(49.59,60.07)
PRUETH0_RXD0: length 72
  TOP w0.121: R31.1 54.74,69.72 55.04,69.72 55.37,70.05 v1(55.37,70.74) U3.43 ; U14.U4 44.17,50.85 44.17,52.12 44.9,52.85 44.9,54.85 47.5,57.45 48.17,57.45 v1(49.28,58.55) ; v1(33.77,46.85) U14.M16
  LYR3 w0.127: v1(33.77,46.85) 32.78,46.85 32.51,47.12 32.51,48.51 32.64,48.64 34.52,48.64 34.96,49.09 34.96,52.62 34.5,53.09 34.5,53.76 34.03,54.23 v1(33.9,54.23)
  LYR4 w0.127: v1(55.37,70.74) 55.32,70.69 55.32,69.96 54.83,69.47 53.47,69.47 52.83,68.83 52.83,66.46 52.68,66.31 50.95,66.31 50.8,66.16 50.8,65.06 50.95,64.91 52.68,64.91 52.83,64.76 52.83,64.26 52.58,64.01 52.58,63.7 52.14,63.26 51.59,63.26 50.97,63.88 48.61,63.88 47.83,63.1 47.83,59.99 v1(49.28,58.55) 47.54,56.81 43.61,56.81 40.51,53.7 39.95,53.7 39.94,53.71 39.09,53.71 38.22,52.83 35.14,52.83 34.42,53.55 34.42,53.76 33.94,54.23 v1(33.9,54.23)
  BOTTOM w0.121: U38.12 52.19,58.31 51.95,58.55 v1(49.28,58.55)
PRUETH0_RXD1: length 74.4
  TOP w0.121: U14.U3 44.97,50.85 44.97,51.72 45.47,52.21 45.47,54.23 47.75,56.52 49.91,56.52 50.89,55.54 v1(50.89,55.5) ; v1(34.57,46.05) U14.L15 ; U3.44 55.87,70.06 v1(55.77,69.96) 55.77,69.74 R32.1
  LYR3 w0.127: v1(34.02,53.59) 34.02,53.02 31.8,50.8 31.27,50.8 30.01,49.54 29.38,49.54 29.37,49.53 29.21,49.53 28.9,49.23 28.81,49.23 28.28,48.7 28.28,46.22 28.51,45.99 28.84,45.99 29.45,45.38 31.56,45.38 31.83,45.64 33.87,45.64 34.27,46.05 v1(34.57,46.05)
  LYR4 w0.127: v1(55.77,69.96) 55.77,68.35 55.48,68.06 54.27,68.06 54.01,68.33 53.67,68.33 53.45,68.11 53.45,67.55 53.85,67.16 53.85,63.85 52.86,62.87 50.15,62.87 50.04,62.98 49.12,62.98 48.7,62.56 48.7,61.86 49.27,61.28 50.23,61.28 50.39,61.12 50.39,58.07 v1(50.55,57.91) 48.77,56.14 43.48,56.14 41.36,54.02 41.36,53.18 40.79,52.6 35.01,52.6 v1(34.02,53.59)
  BOTTOM w0.121: v1(50.89,55.5) U38.14 50.89,57.57 v1(50.55,57.91)
PRUETH0_RXD2: length 38.2
  TOP w0.121: U14.U2 45.77,50.85 46.34,50.85 46.62,51.13 46.62,54.29 48.11,55.79 49.23,55.79 v1(49.59,55.43) ; R33.1 56.37,69.36 56.37,70.72 v1(56.4,70.75) 56.37,70.79 U3.45
  LYR4 w0.127: v1(49.59,55.43) 49.59,55.68 50.94,57.04 52.69,57.04 52.94,57.29 52.94,58.34 51.77,59.52 51.77,61.95 52.18,62.36 53.93,62.36 54.23,62.65 54.23,63.74 54.38,63.89 54.59,63.89 54.74,63.74 54.74,62.65 54.89,62.5 55.65,62.5 56.19,63.05 56.19,63.63 55.92,63.9 55.92,65.57 55.77,65.72 55.27,65.72 55.12,65.87 55.12,66.08 55.27,66.23 55.77,66.23 55.92,66.38 55.92,67.56 56.4,68.05 v1(56.4,70.75)
  BOTTOM w0.121: U38.16 v1(49.59,55.43)
PRUETH0_RXD3: length 37.5
  TOP w0.121: U14.U1 46.42,50.45 46.95,50.99 46.95,54.04 v1(48.29,55.37) ; R34.1 57.28,69.47 v1(57.28,70.23) 56.87,70.64 U3.46
  LYR4 w0.127: v1(48.29,55.37) 48.65,55.01 49.8,55.01 51.44,56.64 55.25,56.64 55.5,56.89 55.5,59.18 55.16,59.52 53.51,59.52 53.21,59.82 53.21,61.06 53.98,61.82 54.67,61.82 54.82,61.67 54.82,61.24 54.97,61.09 55.18,61.09 55.33,61.24 55.33,61.67 55.48,61.82 56.24,61.82 56.93,62.51 56.93,69.89 v1(57.28,70.23)
  BOTTOM w0.121: U38.18 v1(48.29,55.37)
PRUETH0_RXDV: length 66.2
  TOP w0.121: v1(43.37,50.05) U14.T5 ; U3.39 v1(53.37,70.74)
  LYR3 w0.127: v1(48.29,60.33) 48.29,62.64 48.51,62.87 48.78,62.87 48.92,62.72 48.92,61.41 49.07,61.26 49.28,61.26 49.43,61.41 49.43,62.72 49.58,62.87 49.91,62.87 50.06,63.01 50.06,63.86 50.21,64.01 50.42,64.01 50.57,63.86 50.57,63.01 50.72,62.87 51.21,62.87 51.48,63.13 51.48,63.93 51.54,63.99 51.54,64.9 51.39,65.05 49.68,65.05 49.56,65.18 49.56,65.37 49.72,65.52 52.16,65.52 52.28,65.65 52.28,65.89 52.16,66.02 49.56,66.02 49.48,66.1 49.48,66.31 49.62,66.45 50.66,66.45 50.84,66.63 50.84,67.12 51.15,67.43 51.15,67.73 51.3,67.88 51.54,67.88 51.69,68.03 51.69,68.24 51.56,68.37 51.12,68.37 51.02,68.48 51.02,68.52 50.97,68.56 50.97,68.73 51.12,68.88 51.52,68.88 51.69,69.05 51.69,69.26 51.54,69.41 51.3,69.41 51.15,69.56 51.15,69.88 52,70.74 v1(53.37,70.74)
  BOTTOM w0.121: U38.3 v1(48.29,60.33) 47.88,60.33 45.22,57.66 45.22,56.96 43.9,55.64 43.9,54.44 44.68,53.66 44.68,51.11 43.62,50.05 v1(43.37,50.05) ; J18.2 62.23,82.55 60.52,82.55 57.17,79.2 57.17,72.79 TP35.1 56.06,71.68 54.31,71.68 v1(53.37,70.74)
PRUETH0_RXERR: length 65.2
  TOP w0.121: U8.2 36.96,66.17 v1(37.13,66.34) ; v1(34.57,43.65) U14.J15 ; U3.41 v1(54.37,70.74)
  LYR3 w0.127: v1(31.62,53.47) 29.53,51.38 29.06,51.38 26.85,49.16 26.85,46.18 28.16,44.87 28.52,44.51 30.02,44.51 30.38,44.87 33.59,44.87 33.61,44.86 33.92,44.86 34.18,44.6 34.18,44.04 v1(34.57,43.65)
  LYR4 w0.127: v1(31.62,53.47) 31.58,53.51 31.58,54.6 31.95,54.97 31.95,58.43 34.11,60.59 35.66,60.59 37.34,62.27 37.34,66.12 v1(37.13,66.34)
  BOTTOM w0.121: R139.2 37.21,65.79 37.08,65.91 37.08,66.29 v1(37.13,66.34) 37.13,66.63 36.58,67.18 36.58,69.27 36.2,69.64 36.15,69.64 35.54,70.25 35.54,71 35.8,71.26 36.55,71.26 37.06,71.76 41,71.76 49.59,71.76 51.08,70.28 52.49,70.28 53.07,69.7 54.21,69.7 54.37,69.86 v1(54.37,70.74)
PRUETH0_RXERR_COL: length 42.8
  TOP w0.121: v1(71.14,72.83) 71.1,72.78 70.42,72.78 70.21,72.99 U4.6 ; v1(39.07,65.41) 38.96,65.52 U8.4
  LYR3 w0.127: v1(71.14,72.83) 71.03,72.94 69.55,72.94 65.75,76.75 59.5,76.75 54.61,71.85 51.18,71.85 47.59,68.26 47.59,68.13 45.2,65.75 44.89,65.75 44.55,65.41 43.53,65.41 43.11,64.99 39.49,64.99 v1(39.07,65.41)
  BOTTOM w0.121: R139.1 38.95,65.53 v1(39.07,65.41)
PRUETH0_RXERR_COL_PROC: length 64.2
  TOP w0.121: v1(66.67,71.63) 70.53,71.63 71.56,72.65 71.56,73.02 71.3,73.28 70.99,73.28 70.86,73.41 U4.5 ; v1(50.89,59.69) 51.95,58.62 51.95,57.59 51.44,57.07 47.79,57.07 45.21,54.49 45.21,52.57 44.57,51.93 U14.V3
  LYR3 w0.127: v1(66.67,71.63) 65.49,72.81 64.22,72.81 63.72,72.31 63.72,72.07 63.44,71.79 62.82,71.79 62.45,71.42 62.45,71.07 64.84,68.68 65.14,68.68 66.21,67.61 66.21,67.26 65.38,66.44 65.38,64.42 59,58.04 59,55.67 58.33,55 58.33,53.94 57.86,53.47 53.75,53.47 50.99,56.24 50.99,59.59 v1(50.89,59.69)
  BOTTOM w0.121: U38.7 v1(50.89,59.69)
PRUETH0_SPEEDLED: length 36.4
  TOP w0.121: D4.1 64.01,78.88 v1(63.75,79.13) ; v1(67.31,70.61) 67.44,70.48 69.61,70.48 70.21,69.89 U4.3 ; v1(49.02,76.96) R16.1 49.12,77.82 U3.27
  LYR4 w0.127: v1(63.75,79.13) 63.42,79.46 51.52,79.46 v1(49.02,76.96)
  BOTTOM w0.121: v1(63.75,79.13) 63.75,78.61 66.8,75.56 66.8,73.28 67.31,72.77 v1(67.31,70.61) ; TP34.1 v1(49.02,76.96)
PRUETH0_SWSTRAP: length 2.2
  TOP w0.121: U3.21 53.87,81.68 v1(53.9,81.71)
  BOTTOM w0.121: v1(53.9,81.71) 53.85,81.76 R124.1
PRUETH0_TXCLK: length 34.6
  TOP w0.121: v1(54.23,54.56) 52.83,54.56 52.01,53.74 52.01,53.19 51.74,52.92 51.06,52.92 51.05,52.91 50.23,52.91 U14.R1 ; v1(59.41,70.63) 59.39,70.65 59.39,71.59 60.11,72.31 60.11,73.11 59.9,73.32 U3.1 ; U37.18 v1(55.4,60.58)
  LYR3 w0.127: v1(54.23,54.56) 54.98,55.31 54.98,57.4 55.4,57.82 v1(55.4,60.58) 55.84,61.02 55.84,67.1 59.39,70.65 59.39,70.63 v1(59.41,70.63)
PRUETH0_TXD0: length 86.6
  TOP w0.121: U14.T2 45.77,50.05 46.37,50.05 47.33,51.01 47.33,52.6 49.13,54.41 51.62,54.41 52.54,55.33 v1(53.21,55.33) 54.65,55.33 55.29,54.69 57.48,54.69 58,55.2 U37.7 v1(58,58.04) ; U3.3 60.23,74.32 60.23,74.32 60.25,74.32 60.34,74.32 v1(60.88,73.78) ; v1(27.27,46.35) 27.27,45.67 28.36,44.58 29.83,44.58 30.32,44.08 31.38,44.08 31.75,44.45 32.97,44.45 U14.K17
  LYR3 w0.127: v1(58,58.04) 58,58.08 57.4,58.67 57.4,61.72 58.94,63.26 58.94,68.31 59.17,68.54 59.96,68.54 60.69,69.27 60.69,72.78 60.11,73.37 59.62,73.37 59.47,73.22 59.47,72.41 59.32,72.26 59.11,72.26 58.96,72.41 58.96,73.22 58.81,73.37 58.47,73.37 58.29,73.54 58.29,74.03 58.53,74.27 60.38,74.27 60.87,73.78 v1(60.88,73.78) ; v1(32.13,53.16) 32.13,53.15 29.37,50.4 28.62,50.4 27.27,49.04 27.27,46.94 27.27,46.94 v1(27.27,46.35)
  LYR4 w0.127: v1(53.21,55.33) 52.52,55.33 50.4,53.21 48.56,53.21 47.88,53.89 45.89,53.89 43.66,51.66 33.81,51.66 32.31,53.16 v1(32.13,53.16)
PRUETH0_TXD1: length 93.1
  TOP w0.121: v1(33.77,45.25) U14.K16 ; v1(60.41,74.74) 60.32,74.82 U3.4 ; U14.T1 46.34,49.65 47.7,51.01 47.7,52.37 47.83,52.51 49.37,54.04 51.77,54.04 52.64,54.92 53.9,54.92 53.96,54.97 54.5,54.97 55.2,54.27 v1(57.53,54.27) 58.32,54.27 59.3,55.26 U37.9
  LYR3 w0.127: v1(33.53,53.21) 32.45,52.13 31.49,52.13 29.37,50.02 28.83,50.02 27.9,49.08 27.9,45.67 28.42,45.15 33.67,45.15 v1(33.77,45.25) ; v1(57.53,54.27) 57.28,54.53 57.28,57.15 56.86,57.57 56.86,67.56 58.68,69.38 59.37,69.38 60.09,70.11 60.09,71.03 59.88,71.25 58.04,71.25 57.66,71.63 57.66,72 57.51,72.15 56.54,72.15 56.39,72.3 56.39,72.51 56.54,72.66 57.51,72.66 57.66,72.81 57.66,74.17 58.23,74.74 v1(60.41,74.74)
  LYR4 w0.127: v1(33.53,53.21) 34.39,52.35 40.86,52.35 41.66,53.15 41.66,53.77 42.57,54.68 43.66,54.68 43.71,54.63 50.74,54.63 52.25,56.13 53.92,56.13 55.41,54.64 57.16,54.64 v1(57.53,54.27)
